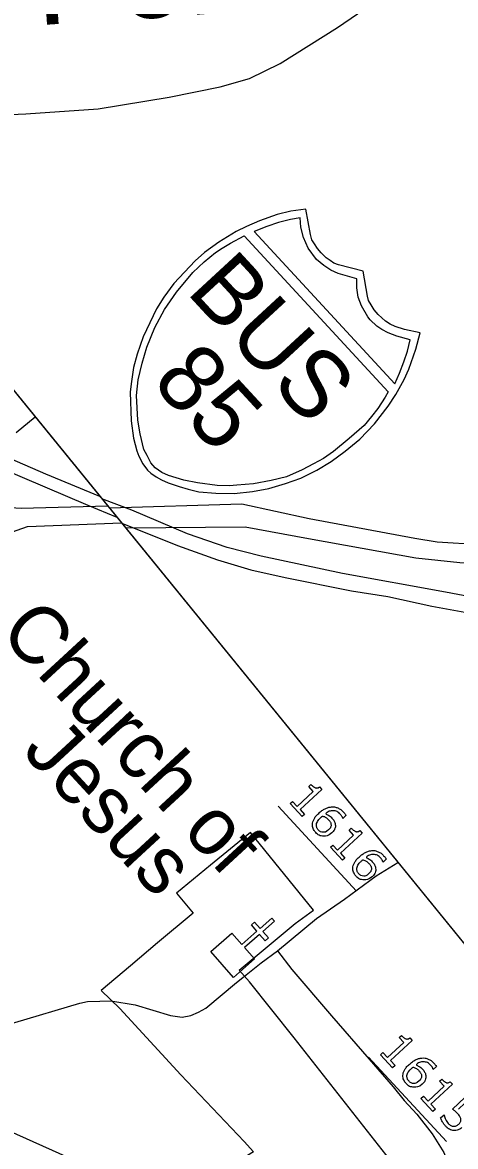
# Model space of a CAD drawing. Extents: x 1695041 to 1706254, y 786537 to 798223.
# Drawn here: x 1702884.8 to 1702961, y 796936.6 to 797134.4 of the extents above; entities that cross this region are included whole.
import ezdxf

# ---------------------------------------------------------------- set-up
doc = ezdxf.new("R2010")
doc.units = 0
for name, color, linetype in [('Default', 7, 'Continuous'), ('Old_Level_13', 7, 'Continuous'), ('Old_Level_27', 7, 'Continuous'), ('Old_Level_32', 7, 'Continuous')]:
    doc.layers.add(name, color=color, linetype=linetype)

msp = doc.modelspace()

# ---------------------------------------------------------------- linework, layer by layer
at = {"layer": 'Default'}
for p, q in [((1702875.54, 797079.09), (1702888.84, 797062.75)), ((1702888.84, 797062.75), (1702992.71, 796935.11)), ((1702929.76, 796996.49), (1702943.55, 796981.56)), ((1702945.68, 796952.31), (1702959.37, 796937.48))]:
    msp.add_line(p, q, dxfattribs=at)
for points in [[(1702807.76, 797162.38), (1703001.1, 796924.8), (1703349.84, 796504.53)], [(1702807.76, 797162.38), (1703001.1, 796924.8), (1703349.84, 796504.53)], [(1702933.64, 797100.02), (1702931.95, 797099.74), (1702929.81, 797099.21), (1702927.75, 797098.49), (1702925.54, 797097.63), (1702950.28, 797070.81), (1702951.09, 797072.72), (1702951.88, 797074.68), (1702952.51, 797076.56), (1702952.96, 797078.55), (1702950.62, 797079.18), (1702949.09, 797079.8), (1702947.98, 797080.4), (1702947.12, 797080.99), (1702945.96, 797082.06), (1702945.52, 797082.6), (1702944.4, 797084.55), (1702943.83, 797086.05), (1702943.57, 797087.73), (1702943.58, 797089.3), (1702940.34, 797090.24), (1702939.05, 797090.8), (1702937.78, 797091.62), (1702936.53, 797092.67), (1702935.04, 797094.68), (1702934.21, 797096.57), (1702933.72, 797098.4), (1702933.64, 797100.02)], [(1702883.66, 797062.24), (1702887.03, 797064.98), (1702987.82, 796941.19)], [(1702883.66, 797062.24), (1702887.03, 797064.98), (1702987.82, 796941.19)], [(1702899.82, 797049.26), (1702884.52, 797048.87), (1702853.34, 797050.9), (1702810.22, 797054.4), (1702764.62, 797057.1), (1702726.9, 797059.44), (1702698.94, 797061.93)], [(1703285.6, 797010.59), (1703269.14, 797015.21), (1703259.82, 797017.34), (1703223.36, 797020.86), (1703137.92, 797027.32), (1703108.37, 797031.02), (1703096.16, 797034.26), (1703081.92, 797034.91), (1703062.04, 797036.28), (1703040.38, 797037.67), (1703020.02, 797038.85), (1703002.94, 797039.89), (1702982.67, 797041.42), (1702965.31, 797042.47), (1702957.75, 797042.96), (1702953.78, 797043.59), (1702935.24, 797047.06), (1702923.39, 797049.63), (1702900.08, 797048.94)], [(1702688.34, 796982.35), (1702718.24, 796991.79), (1702764.72, 797006.91), (1702802.16, 797018.72), (1702853.59, 797034.32), (1702885.65, 797045.69), (1702902.18, 797046.36)], [(1703289.7, 797006.43), (1703268.17, 797012.44), (1703259.5, 797014.41), (1703251.47, 797015.1), (1703235.43, 797016.24), (1703213.94, 797018.14), (1703191.44, 797019.88), (1703168.84, 797021.51), (1703144.25, 797023.35), (1703122.49, 797025.14), (1703108.81, 797026.43), (1703095.3, 797030.24), (1703081.37, 797031.4), (1703060.9, 797032.87), (1703035.99, 797034.53), (1703015.51, 797035.99), (1702993.46, 797037.4), (1702976.12, 797038.31), (1702961.7, 797039.29), (1702953.95, 797040.12), (1702935.07, 797043.53), (1702923.94, 797045.61), (1702903.01, 797045.39)], [(1702925.41, 796935.68), (1702910.71, 796926.62), (1702880.93, 796939.99), (1702820.56, 796887.72), (1702793.87, 796908.61), (1702789.51, 796910.51), (1702766.84, 796932.24), (1702771.83, 796939.94), (1702770.51, 796956.02), (1702774.36, 796959.43), (1702767.63, 796967.11), (1702772.81, 796971.72), (1702783.62, 796979.72), (1702783.43, 796981.21), (1702797.1, 796993.15), (1702779.26, 797011.19), (1702762.34, 797007.42), (1702760.1, 797010.1), (1702716.96, 796974.07), (1702714.33, 796993.89), (1702694.56, 796987.03), (1702684.89, 796991.85), (1702683.46, 796987.65)], [(1702925.41, 796935.68), (1702910.71, 796926.62), (1702880.93, 796939.99), (1702820.56, 796887.72), (1702793.87, 796908.61), (1702789.51, 796910.51), (1702766.84, 796932.24), (1702771.83, 796939.94), (1702770.51, 796956.02), (1702774.36, 796959.43), (1702767.63, 796967.11), (1702772.81, 796971.72), (1702783.62, 796979.72), (1702783.43, 796981.21), (1702797.1, 796993.15), (1702779.26, 797011.19), (1702762.34, 797007.42), (1702760.1, 797010.1), (1702716.96, 796974.07), (1702714.33, 796993.89), (1702694.56, 796987.03), (1702684.89, 796991.85), (1702683.46, 796987.65)], [(1702933.97, 796994.66), (1702931.85, 796996.95), (1702932.29, 796997.35), (1702933.1, 796996.47), (1702935.94, 796999.1), (1702935.13, 796999.98), (1702935.52, 797000.34)], [(1702937.02, 796999.9), (1702937.43, 796999.45), (1702933.61, 796995.92), (1702934.41, 796995.06), (1702933.97, 796994.66)], [(1702941.68, 796994.85), (1702941.13, 796994.34), (1702941.11, 796994.37)], [(1702941.07, 796986.97), (1702938.95, 796989.26), (1702939.39, 796989.66), (1702940.2, 796988.78), (1702943.04, 796991.4), (1702942.23, 796992.29), (1702942.62, 796992.65)], [(1702944.12, 796992.2), (1702944.53, 796991.76), (1702940.71, 796988.23), (1702941.51, 796987.37), (1702941.07, 796986.97)], [(1702969.78, 796940.73), (1702969.33, 796939.28), (1702965.99, 796925.42), (1702964.15, 796917.75), (1702962.89, 796917.17), (1702932.55, 796955.73), (1702924.73, 796965.57), (1702922.88, 796967.64), (1702932.74, 796975.84), (1702936, 796978.21), (1702924.89, 796991.85), (1702917.84, 796986.09), (1702911.88, 796981.22), (1702914.79, 796977.7), (1702908.54, 796972.43), (1702903.8, 796968.42), (1702898.61, 796964.04), (1702901.91, 796960.89), (1702912.63, 796949.21), (1702923.77, 796937.5), (1702925.41, 796935.68)], [(1702969.78, 796940.73), (1702969.33, 796939.28), (1702965.99, 796925.42), (1702964.15, 796917.75), (1702962.89, 796917.17), (1702932.55, 796955.73), (1702924.73, 796965.57), (1702922.88, 796967.64), (1702932.74, 796975.84), (1702936, 796978.21), (1702924.89, 796991.85), (1702917.84, 796986.09), (1702911.88, 796981.22), (1702914.79, 796977.7), (1702908.54, 796972.43), (1702903.8, 796968.42), (1702898.61, 796964.04), (1702901.91, 796960.89), (1702912.63, 796949.21), (1702923.77, 796937.5), (1702925.41, 796935.68)], [(1702948.78, 796987.16), (1702948.23, 796986.65), (1702948.21, 796986.68)], [(1702929.65, 796971.07), (1702932.14, 796967.77), (1702939.12, 796959.62), (1702945.77, 796951.98), (1702950, 796947.1), (1702951.94, 796944.71), (1702954.16, 796942.3), (1702956.83, 796938.82), (1702958.88, 796935.58), (1702960.04, 796932.69)], [(1702949.89, 796950.48), (1702947.77, 796952.77), (1702948.2, 796953.17), (1702949.02, 796952.29), (1702951.86, 796954.92), (1702951.05, 796955.8), (1702951.43, 796956.16)], [(1702952.94, 796955.72), (1702953.35, 796955.27), (1702949.52, 796951.74), (1702950.32, 796950.88), (1702949.89, 796950.48)], [(1702957.6, 796950.67), (1702957.05, 796950.16), (1702957.02, 796950.19)], [(1702956.99, 796942.79), (1702954.87, 796945.08), (1702955.3, 796945.48), (1702956.12, 796944.6), (1702958.96, 796947.22), (1702958.15, 796948.11), (1702958.53, 796948.47)], [(1702960.04, 796948.02), (1702960.45, 796947.58), (1702956.62, 796944.05), (1702957.42, 796943.19), (1702956.99, 796942.79)], [(1702960.41, 796943.21), (1702962.59, 796945.23), (1702964.95, 796942.68), (1702964.45, 796942.22), (1702962.6, 796944.22), (1702961.47, 796943.18)], [(1702958.34, 796941.64), (1702958.94, 796942.2), (1702958.98, 796942.16)]]:
    msp.add_lwpolyline(points, dxfattribs=at)
for points in [[(1702906.79, 797055.63), (1702907.38, 797055.09), (1702908.27, 797054.44), (1702909.23, 797053.91), (1702910.43, 797053.39), (1702912.34, 797052.75), (1702913.91, 797052.28), (1702915.83, 797051.82), (1702918.8, 797051.56), (1702922, 797051.51), (1702925.24, 797051.86), (1702928.09, 797052.39), (1702931.07, 797053.3), (1702933.77, 797054.23), (1702936.57, 797055.6), (1702939.1, 797057.12), (1702941.53, 797058.95), (1702944.12, 797061.07), (1702946.73, 797063.79), (1702949.12, 797066.88), (1702950.47, 797068.96), (1702951.94, 797071.59), (1702952.77, 797073.4), (1702953.97, 797076.89), (1702954.73, 797079.76), (1702951.98, 797080.35), (1702950.37, 797080.91), (1702949.45, 797081.31), (1702948.67, 797081.87), (1702947.34, 797083), (1702946.64, 797083.84), (1702946.12, 797084.74), (1702945.68, 797085.49), (1702945.46, 797086.24), (1702944.7, 797090.62), (1702940.38, 797091.73), (1702939.58, 797092.07), (1702938.92, 797092.54), (1702938.23, 797092.97), (1702937.32, 797093.86), (1702936.68, 797094.6), (1702936.13, 797095.46), (1702935.71, 797096.16), (1702935.43, 797097.1), (1702934.62, 797101.55), (1702932, 797101.17), (1702929.59, 797100.61), (1702926.48, 797099.51), (1702924.21, 797098.51), (1702922.39, 797097.62), (1702919.31, 797095.73), (1702916.79, 797093.9), (1702915.14, 797092.47), (1702911.4, 797088.47), (1702909.67, 797086.06), (1702908.36, 797084.02), (1702906, 797079.09), (1702904.94, 797076.05), (1702904.32, 797073.71), (1702903.87, 797070.81), (1702903.74, 797069.34), (1702903.87, 797064.31), (1702904.32, 797061.28), (1702904.89, 797059.05), (1702905.27, 797058.11), (1702905.97, 797056.74)], [(1702933.64, 797100.02), (1702931.95, 797099.74), (1702929.81, 797099.21), (1702927.75, 797098.49), (1702925.54, 797097.63), (1702950.28, 797070.81), (1702951.09, 797072.72), (1702951.88, 797074.68), (1702952.51, 797076.56), (1702952.96, 797078.55), (1702950.62, 797079.18), (1702949.09, 797079.8), (1702947.98, 797080.4), (1702947.12, 797080.99), (1702945.96, 797082.06), (1702945.52, 797082.6), (1702944.4, 797084.55), (1702943.83, 797086.05), (1702943.57, 797087.73), (1702943.58, 797089.3), (1702940.34, 797090.24), (1702939.05, 797090.8), (1702937.78, 797091.62), (1702936.53, 797092.67), (1702935.04, 797094.68), (1702934.21, 797096.57), (1702933.72, 797098.4)], [(1702949.1, 797069.43), (1702948.61, 797068.44), (1702947.29, 797066.49), (1702946.19, 797065.09), (1702944.89, 797063.5), (1702942.27, 797061.22), (1702939.51, 797058.9), (1702937.72, 797057.7), (1702935.99, 797056.71), (1702934, 797055.69), (1702931.24, 797054.47), (1702928.55, 797053.81), (1702925.43, 797053.22), (1702922.47, 797052.96), (1702921.21, 797052.88), (1702919.04, 797052.91), (1702915.58, 797053.42), (1702913.14, 797053.88), (1702910.49, 797054.67), (1702909.28, 797055.2), (1702908.1, 797056.03), (1702907.38, 797056.94), (1702906.7, 797058.23), (1702906.15, 797059.27), (1702905.46, 797062.01), (1702905.08, 797064.41), (1702904.82, 797068.75), (1702905.15, 797071.52), (1702905.83, 797074.46), (1702906.68, 797077.29), (1702908.05, 797080.75), (1702909.75, 797083.88), (1702911.87, 797086.95), (1702914.76, 797090.38), (1702916.71, 797092.27), (1702918.74, 797093.92), (1702919.91, 797094.66), (1702921.38, 797095.57), (1702923.76, 797096.86)], [(1702921.63, 796974.15), (1702923.37, 796972.18), (1702926.01, 796974.5), (1702925.04, 796975.61), (1702925.59, 796976.1), (1702926.57, 796974.99), (1702928.65, 796976.82), (1702929.14, 796976.27), (1702927.06, 796974.43), (1702928.03, 796973.32), (1702927.48, 796972.83), (1702926.5, 796973.94), (1702923.86, 796971.62), (1702925.62, 796969.62), (1702921.92, 796966.37), (1702917.94, 796970.9)]]:
    msp.add_lwpolyline(points, close=True, dxfattribs=at)
for points in [[(1702935.52, 797000.34), (1702935.68, 797000.16), (1702935.9, 796999.98), (1702936.12, 796999.8), (1702936.28, 796999.75), (1702936.47, 796999.68), (1702936.65, 796999.71), (1702936.83, 796999.74), (1702937.02, 796999.9)], [(1702939.18, 796991.78), (1702938.53, 796991.18), (1702937.73, 796991.23), (1702936.93, 796991.28), (1702936.36, 796991.89), (1702936.07, 796992.21), (1702935.93, 796992.55), (1702935.79, 796992.9), (1702935.8, 796993.27), (1702935.81, 796993.74), (1702936.08, 796994.23), (1702936.34, 796994.72), (1702936.89, 796995.23), (1702937.46, 796995.75), (1702938.01, 796996.03), (1702938.55, 796996.31), (1702939.14, 796996.36), (1702939.69, 796996.41), (1702940.24, 796996.18), (1702940.79, 796995.95), (1702941.27, 796995.42), (1702941.43, 796995.25), (1702941.52, 796995.13), (1702941.61, 796995), (1702941.68, 796994.85)], [(1702938.62, 796992.33), (1702938.88, 796992.58), (1702938.99, 796992.81), (1702939.09, 796993.05), (1702939.05, 796993.35), (1702939.02, 796993.57), (1702938.9, 796993.75), (1702938.78, 796993.94), (1702938.62, 796994.11), (1702938.4, 796994.35), (1702938.15, 796994.51), (1702937.9, 796994.66), (1702937.58, 796994.77), (1702937.51, 796994.72), (1702937.45, 796994.67), (1702937.39, 796994.62), (1702937.3, 796994.54), (1702936.85, 796994.12), (1702936.68, 796993.79), (1702936.5, 796993.45), (1702936.5, 796993.15), (1702936.5, 796992.91), (1702936.58, 796992.7), (1702936.66, 796992.49), (1702936.83, 796992.32), (1702937.21, 796991.9), (1702937.68, 796991.9), (1702938.15, 796991.9), (1702938.62, 796992.33)], [(1702941.11, 796994.37), (1702941.08, 796994.49), (1702940.97, 796994.69), (1702940.86, 796994.89), (1702940.7, 796995.05), (1702940.14, 796995.67), (1702939.42, 796995.68), (1702938.7, 796995.69), (1702937.99, 796995.14), (1702938.36, 796995.04), (1702938.65, 796994.88), (1702938.94, 796994.71), (1702939.22, 796994.41), (1702939.47, 796994.14), (1702939.61, 796993.89), (1702939.75, 796993.64), (1702939.8, 796993.28), (1702939.85, 796992.87), (1702939.71, 796992.5), (1702939.56, 796992.13), (1702939.18, 796991.78)], [(1702942.62, 796992.65), (1702942.78, 796992.47), (1702943, 796992.29), (1702943.22, 796992.11), (1702943.38, 796992.06), (1702943.57, 796991.99), (1702943.75, 796992.02), (1702943.93, 796992.04), (1702944.12, 796992.2)], [(1702946.28, 796984.08), (1702945.63, 796983.49), (1702944.83, 796983.54), (1702944.03, 796983.58), (1702943.46, 796984.2), (1702943.17, 796984.52), (1702943.03, 796984.86), (1702942.89, 796985.21), (1702942.9, 796985.58), (1702942.91, 796986.04), (1702943.18, 796986.54), (1702943.44, 796987.03), (1702943.99, 796987.54), (1702944.56, 796988.06), (1702945.11, 796988.34), (1702945.65, 796988.62), (1702946.24, 796988.67), (1702946.79, 796988.72), (1702947.34, 796988.49), (1702947.89, 796988.26), (1702948.37, 796987.73), (1702948.53, 796987.56), (1702948.62, 796987.44), (1702948.71, 796987.31), (1702948.78, 796987.16)], [(1702945.72, 796984.64), (1702945.98, 796984.88), (1702946.09, 796985.12), (1702946.19, 796985.36), (1702946.15, 796985.66), (1702946.12, 796985.87), (1702946, 796986.06), (1702945.88, 796986.24), (1702945.72, 796986.42), (1702945.5, 796986.66), (1702945.25, 796986.82), (1702945, 796986.97), (1702944.68, 796987.08), (1702944.61, 796987.03), (1702944.55, 796986.98), (1702944.49, 796986.92), (1702944.4, 796986.84), (1702943.95, 796986.43), (1702943.78, 796986.1), (1702943.6, 796985.76), (1702943.6, 796985.46), (1702943.6, 796985.22), (1702943.68, 796985.01), (1702943.76, 796984.8), (1702943.93, 796984.62), (1702944.31, 796984.21), (1702944.78, 796984.21), (1702945.25, 796984.2), (1702945.72, 796984.64)], [(1702948.21, 796986.68), (1702948.18, 796986.8), (1702948.07, 796987), (1702947.96, 796987.19), (1702947.8, 796987.36), (1702947.24, 796987.97), (1702946.52, 796987.98), (1702945.8, 796988), (1702945.09, 796987.45), (1702945.46, 796987.35), (1702945.75, 796987.19), (1702946.04, 796987.02), (1702946.32, 796986.72), (1702946.57, 796986.45), (1702946.71, 796986.2), (1702946.85, 796985.94), (1702946.9, 796985.59), (1702946.95, 796985.18), (1702946.81, 796984.81), (1702946.66, 796984.43), (1702946.28, 796984.08)], [(1702951.43, 796956.16), (1702951.6, 796955.98), (1702951.82, 796955.8), (1702952.04, 796955.62), (1702952.19, 796955.57), (1702952.39, 796955.5), (1702952.57, 796955.53), (1702952.74, 796955.56), (1702952.94, 796955.72)], [(1702955.1, 796947.6), (1702954.45, 796947), (1702953.65, 796947.05), (1702952.84, 796947.1), (1702952.27, 796947.71), (1702951.98, 796948.03), (1702951.84, 796948.37), (1702951.71, 796948.72), (1702951.71, 796949.09), (1702951.72, 796949.56), (1702951.99, 796950.05), (1702952.26, 796950.54), (1702952.81, 796951.05), (1702953.38, 796951.57), (1702953.92, 796951.85), (1702954.47, 796952.13), (1702955.06, 796952.18), (1702955.61, 796952.23), (1702956.16, 796952), (1702956.7, 796951.77), (1702957.19, 796951.24), (1702957.35, 796951.07), (1702957.44, 796950.95), (1702957.53, 796950.82), (1702957.6, 796950.67)], [(1702957.02, 796950.19), (1702956.99, 796950.31), (1702956.88, 796950.51), (1702956.78, 796950.71), (1702956.62, 796950.87), (1702956.06, 796951.49), (1702955.34, 796951.5), (1702954.62, 796951.51), (1702953.91, 796950.96), (1702954.27, 796950.86), (1702954.56, 796950.7), (1702954.85, 796950.54), (1702955.13, 796950.23), (1702955.38, 796949.96), (1702955.53, 796949.71), (1702955.67, 796949.46), (1702955.71, 796949.1), (1702955.77, 796948.69), (1702955.62, 796948.32), (1702955.48, 796947.95), (1702955.1, 796947.6)], [(1702954.54, 796948.15), (1702954.8, 796948.4), (1702954.9, 796948.63), (1702955, 796948.87), (1702954.97, 796949.17), (1702954.94, 796949.39), (1702954.82, 796949.57), (1702954.7, 796949.76), (1702954.54, 796949.93), (1702954.32, 796950.17), (1702954.07, 796950.33), (1702953.82, 796950.48), (1702953.5, 796950.59), (1702953.43, 796950.54), (1702953.37, 796950.49), (1702953.31, 796950.44), (1702953.22, 796950.36), (1702952.77, 796949.94), (1702952.6, 796949.61), (1702952.42, 796949.27), (1702952.42, 796948.97), (1702952.41, 796948.73), (1702952.5, 796948.52), (1702952.58, 796948.32), (1702952.74, 796948.14), (1702953.13, 796947.72), (1702953.6, 796947.72), (1702954.07, 796947.72), (1702954.54, 796948.15)], [(1702958.53, 796948.47), (1702958.7, 796948.29), (1702958.92, 796948.11), (1702959.14, 796947.93), (1702959.29, 796947.88), (1702959.49, 796947.81), (1702959.66, 796947.84), (1702959.84, 796947.86), (1702960.04, 796948.02)], [(1702958.98, 796942.16), (1702959.04, 796941.79), (1702959.23, 796941.38), (1702959.41, 796940.97), (1702959.69, 796940.67), (1702959.88, 796940.46), (1702960.11, 796940.33), (1702960.34, 796940.19), (1702960.62, 796940.17), (1702960.86, 796940.16), (1702961.09, 796940.25), (1702961.32, 796940.35), (1702961.55, 796940.56), (1702961.77, 796940.76), (1702961.85, 796940.98), (1702961.93, 796941.19), (1702961.9, 796941.41), (1702961.87, 796941.66), (1702961.72, 796941.91), (1702961.57, 796942.16), (1702961.33, 796942.43), (1702961.09, 796942.68), (1702960.85, 796942.88), (1702960.6, 796943.08), (1702960.41, 796943.21)], [(1702962.08, 796939.98), (1702961.78, 796939.7), (1702961.41, 796939.56), (1702961.04, 796939.42), (1702960.68, 796939.44), (1702960.29, 796939.46), (1702959.92, 796939.64), (1702959.56, 796939.83), (1702959.21, 796940.2), (1702958.89, 796940.55), (1702958.66, 796940.94), (1702958.44, 796941.33), (1702958.34, 796941.64)]]:
    msp.add_open_spline(points, degree=3, dxfattribs=at)
at = {"layer": 'Old_Level_13'}
msp.add_lwpolyline([(1702867.71, 797117.51), (1702873.24, 797117.79), (1702885.37, 797118.35), (1702898.08, 797119.2), (1702910.59, 797121.24), (1702919.58, 797123.06), (1702924.74, 797124.52), (1702930.1, 797127.16), (1702940.21, 797133.51), (1702950.94, 797140.93)], dxfattribs=at)
at = {"layer": 'Old_Level_27'}
for points in [[(1702784.25, 797097.34), (1702797.83, 797091.41), (1702813.84, 797084.75), (1702836.68, 797075.28), (1702855.59, 797066.8), (1702865.93, 797062.34), (1702896.29, 797049.49), (1702901.38, 797047.34)], [(1702898.4, 797051.01), (1702888.89, 797054.9), (1702876.16, 797060.44), (1702841.67, 797075.38), (1702823.45, 797083.12), (1702803.73, 797091.37)], [(1702971.01, 797031.9), (1702959.22, 797034.13), (1702941.06, 797037.42), (1702926.76, 797040.48), (1702920.77, 797042.04), (1702913.78, 797044.41), (1702904, 797048.61), (1702898.74, 797050.59)], [(1702902.23, 797046.29), (1702912.02, 797042.37), (1702919.1, 797039.86), (1702924.96, 797038.1), (1702930.98, 797036.75), (1702942.66, 797034.4), (1702949.03, 797033.38), (1702956.77, 797031.69), (1702963.25, 797030.5), (1702970.63, 797029.15)]]:
    msp.add_lwpolyline(points, dxfattribs=at)
at = {"layer": 'Old_Level_32'}
for points in [[(1702929.65, 796971.07), (1702936.53, 796976.71), (1702941.4, 796980.16), (1702947.02, 796984.26), (1702950.84, 796986.56)], [(1702923.52, 796966.35), (1702926.75, 796968.93), (1702929.65, 796971.07)], [(1702898.39, 796962.2), (1702900.3, 796962.25), (1702904.58, 796961.55), (1702910.8, 796959.67), (1702912.87, 796959.36), (1702914.42, 796959.65), (1702915.77, 796960.25), (1702917.04, 796960.98), (1702922.4, 796965.45), (1702923.52, 796966.35)], [(1702789.79, 796910.41), (1702799.56, 796914.01), (1702813.28, 796918.99), (1702822.2, 796922.52), (1702826.4, 796924.64), (1702832.11, 796929.1), (1702840.04, 796935.72), (1702849.05, 796942.09), (1702861.71, 796950.19), (1702864.47, 796951.59), (1702869.27, 796953.44), (1702883.42, 796958.45), (1702894.89, 796961.85), (1702896.19, 796962.14), (1702898.39, 796962.2)]]:
    msp.add_lwpolyline(points, dxfattribs=at)

# ---------------------------------------------------------------- texts
at = {"layer": 'Default'}
for s, height, rotation, p in [('High Point', 16.378, 3.8316, (1702836.29, 797130.47)), ('BUS', 11.837, 312.7091, (1702913.4, 797086.98)), ('85', 11.837, 312.7091, (1702907.26, 797071.03)), ('Church of', 10.146, 312.7091, (1702880.46, 797026.95)), (' Jesus', 10.146, 312.7091, (1702881.94, 797008.82)), ('Gospel Way', 9.224, 312.7091, (1702861.66, 796935.69))]:
    msp.add_text(s, height=height, rotation=rotation, dxfattribs=at).set_placement(p)

doc.saveas('drawing.dxf')
